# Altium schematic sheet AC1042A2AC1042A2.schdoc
size 127 x 101 mm
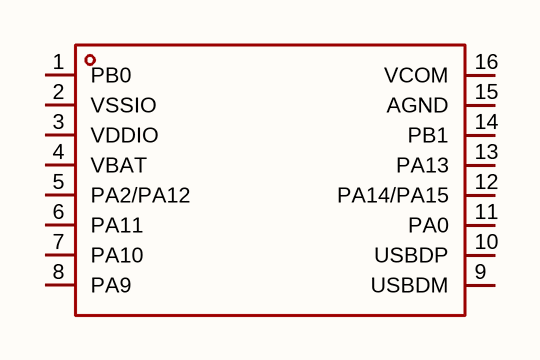
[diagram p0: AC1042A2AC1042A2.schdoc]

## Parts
U?  ac1042a2  [SOP-16_L10.0-W4.0-P1.27-LS6.0-BL]  (value not drawn)

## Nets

Not connected (* = marked no-connect by the designer): U? 1(PB0) 2(VSSIO) 3(VDDIO) 4(VBAT) 5(PA2/PA12) 6(PA11) 7(PA10) 8(PA9) 9(USBDM) 10(USBDP) 11(PA0) 12(PA14/PA15) 13(PA13) 14(PB1) 15(AGND) 16(VCOM)

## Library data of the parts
U? = ac1042a2: CPU内核:-;CPU最大主频:160MHz;CPU位数:32bit;; Manufacturer: JL(杰理); AddInBom: yes; ModelId: ee0e272ebf01490fae8942030b5217f4; ModelTransform: 393.7,236.22,0,0,0,0,0,0,0; CPU Maximum Speed: 160MHz; Core Size: 32bit; ADC (Bit): 16bit；10bit; DAC (Bit): 16bit; Voltage - Supply: 2V~5V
